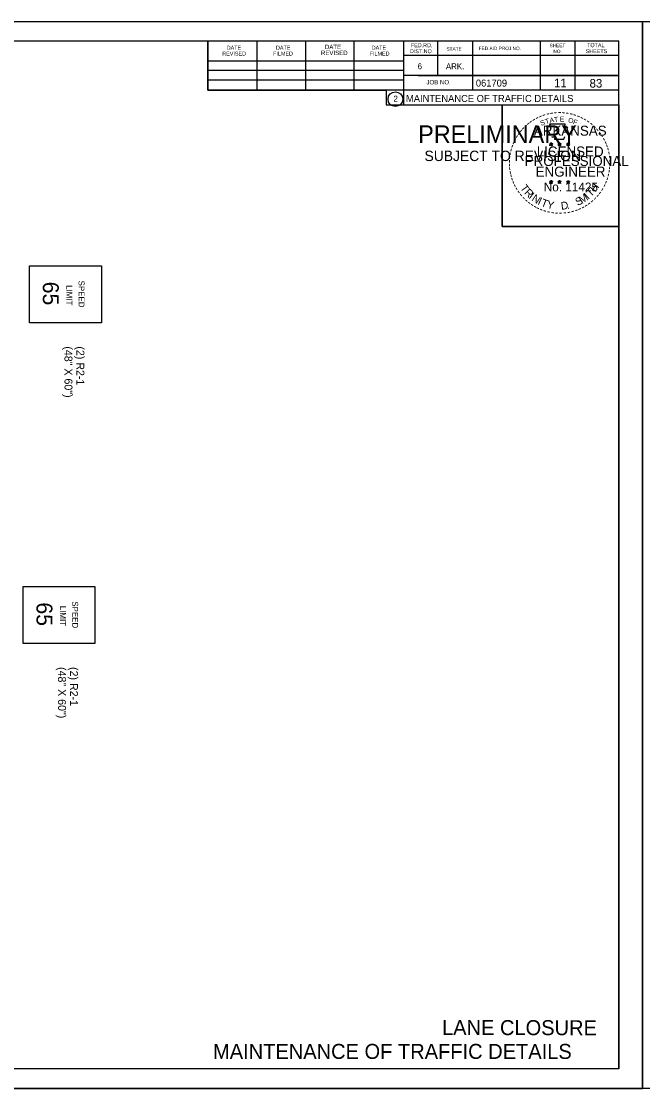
# Model space of a CAD drawing. Extents: x 1397271 to 1411271, y 376395 to 377888.
# Drawn here: x 1408068 to 1408938, y 376395 to 377888 of the extents above; entities that cross this region are included whole.
import ezdxf

# ---------------------------------------------------------------- set-up
doc = ezdxf.new("R2010")
doc.units = 0
for name, color, linetype in [('Default', 7, 'Continuous'), ('R_Border', 7, 'Continuous'), ('R_Border PE', 7, 'Continuous'), ('R_Border Prem', 7, 'Continuous'), ('R_Draft', 7, 'Continuous'), ('R_MOT', 7, 'Continuous'), ('R_No Plot', 7, 'Continuous')]:
    doc.layers.add(name, color=color, linetype=linetype)

msp = doc.modelspace()

# ---------------------------------------------------------------- linework, layer by layer
at = {"layer": 'R_Border'}
for p, q in [((1406691.4, 377860.7), (1408904.7, 377860.7)), ((1408328.9, 377791.6), (1408328.9, 377860.7)), ((1408397.9, 377791.6), (1408397.9, 377859.3)), ((1408466.2, 377791.6), (1408466.2, 377859.3)), ((1408534, 377791.6), (1408534, 377859.3)), ((1408603, 377860.7), (1408603, 377771.1)), ((1408650.9, 377860.7), (1408650.9, 377812.1)), ((1408699.5, 377860.7), (1408699.5, 377791.6)), ((1408794.5, 377860.7), (1408794.5, 377791.6)), ((1408843.1, 377860.7), (1408843.1, 377791.6)), ((1408904.7, 376422.5), (1408904.7, 377860.7)), ((1408328.9, 377832.6), (1408603, 377832.6)), ((1408904.7, 377840.1), (1408603, 377840.1)), ((1408904.7, 377840.3), (1408904.7, 377840.3)), ((1408328.9, 377819.6), (1408603, 377819.6)), ((1408328.9, 377791.6), (1408328.9, 377806)), ((1408328.9, 377806), (1408603, 377806)), ((1408904.7, 377812.1), (1408603, 377812.1)), ((1408623.7, 377812.1), (1408904.7, 377812.1)), ((1408904.7, 377791.6), (1408328.9, 377791.6)), ((1408603, 377771.1), (1408904.7, 377771.1)), ((1408904.7, 376422.5), (1406691.4, 376422.5))]:
    msp.add_line(p, q, dxfattribs=at)
msp.add_circle((1408591.7, 377779.1), 10.3, dxfattribs=at)
at = {"layer": 'R_Border PE'}
for p, q in [((1408807.3, 377716.8), (1408809.7, 377716.1)), ((1408807.3, 377716.8), (1408809.1, 377716.5)), ((1408807.3, 377716.8), (1408809, 377716)), ((1408808.2, 377714), (1408809.7, 377716.1)), ((1408808.2, 377714), (1408809.1, 377715.7)), ((1408808.2, 377714), (1408809.7, 377715.5)), ((1408809.7, 377718.6), (1408809.5, 377716.9)), ((1408809.7, 377716.1), (1408809.7, 377718.6)), ((1408809.7, 377718.6), (1408810.1, 377716.9)), ((1408812.2, 377716.8), (1408809.7, 377716.1)), ((1408811.2, 377714), (1408809.7, 377716.1)), ((1408811.2, 377714), (1408809.7, 377715.5)), ((1408812.2, 377716.8), (1408810.2, 377716.5)), ((1408811.2, 377714), (1408810.3, 377716)), ((1408812.2, 377716.8), (1408810.7, 377716.1)), ((1408819, 377716.8), (1408821.4, 377716.1)), ((1408819, 377716.8), (1408820.8, 377716.5)), ((1408819, 377716.8), (1408820.7, 377716)), ((1408819.9, 377714), (1408821.4, 377716.1)), ((1408819.9, 377714), (1408820.8, 377715.7)), ((1408819.9, 377714), (1408821.4, 377715.5)), ((1408821.4, 377718.6), (1408821.1, 377716.9)), ((1408821.4, 377716.1), (1408821.4, 377718.6)), ((1408821.4, 377718.6), (1408821.8, 377716.9)), ((1408823.9, 377716.8), (1408821.4, 377716.1)), ((1408822.9, 377714), (1408821.4, 377716.1)), ((1408822.9, 377714), (1408821.4, 377715.5)), ((1408823.9, 377716.8), (1408821.9, 377716.5)), ((1408822.9, 377714), (1408822, 377716)), ((1408823.9, 377716.8), (1408822.4, 377716.1)), ((1408831.3, 377716.8), (1408833.8, 377716)), ((1408831.3, 377716.8), (1408833.1, 377716.4)), ((1408831.3, 377716.8), (1408833, 377715.9)), ((1408832.3, 377713.9), (1408833.8, 377716)), ((1408832.3, 377713.9), (1408833.2, 377715.6)), ((1408832.3, 377713.9), (1408833.8, 377715.4)), ((1408833.8, 377718.5), (1408833.5, 377716.8)), ((1408833.8, 377716), (1408833.8, 377718.5)), ((1408833.8, 377718.5), (1408834.1, 377716.8)), ((1408836.2, 377716.8), (1408833.8, 377716)), ((1408835.3, 377713.9), (1408833.8, 377716)), ((1408835.3, 377713.9), (1408833.8, 377715.4)), ((1408836.2, 377716.8), (1408834.2, 377716.4)), ((1408835.3, 377713.9), (1408834.3, 377715.9)), ((1408836.2, 377716.8), (1408834.8, 377716)), ((1408807.3, 377663.8), (1408809.7, 377663.1)), ((1408807.3, 377663.8), (1408809, 377663.5)), ((1408807.3, 377663.8), (1408808.9, 377663)), ((1408809.7, 377665.6), (1408809.4, 377663.8)), ((1408809.7, 377663.1), (1408809.7, 377665.6)), ((1408809.7, 377665.6), (1408810.1, 377663.9)), ((1408812.1, 377663.8), (1408809.7, 377663.1)), ((1408812.1, 377663.8), (1408810.1, 377663.5)), ((1408812.1, 377663.8), (1408810.7, 377663.1)), ((1408819, 377663.8), (1408821.4, 377663.1)), ((1408819, 377663.8), (1408820.7, 377663.5)), ((1408819, 377663.8), (1408820.6, 377663)), ((1408821.4, 377665.6), (1408821.1, 377663.8)), ((1408821.4, 377663.1), (1408821.4, 377665.6)), ((1408821.4, 377665.6), (1408821.7, 377663.9)), ((1408823.8, 377663.8), (1408821.4, 377663.1)), ((1408823.8, 377663.8), (1408821.8, 377663.5)), ((1408823.8, 377663.8), (1408822.4, 377663.1)), ((1408831.3, 377663.8), (1408833.8, 377663)), ((1408831.3, 377663.8), (1408833.1, 377663.4)), ((1408831.3, 377663.8), (1408833, 377662.9)), ((1408833.8, 377665.5), (1408833.5, 377663.8)), ((1408833.8, 377663), (1408833.8, 377665.5)), ((1408833.8, 377665.5), (1408834.1, 377663.8)), ((1408836.2, 377663.8), (1408833.8, 377663)), ((1408836.2, 377663.8), (1408834.2, 377663.4)), ((1408836.2, 377663.8), (1408834.8, 377663)), ((1408808.2, 377661), (1408809.7, 377663.1)), ((1408808.2, 377661), (1408809.1, 377662.7)), ((1408808.2, 377661), (1408809.7, 377662.5)), ((1408811.2, 377661), (1408809.7, 377663.1)), ((1408811.2, 377661), (1408809.7, 377662.5)), ((1408811.2, 377661), (1408810.2, 377663)), ((1408819.9, 377661), (1408821.4, 377663.1)), ((1408819.9, 377661), (1408820.8, 377662.7)), ((1408819.9, 377661), (1408821.4, 377662.5)), ((1408822.9, 377661), (1408821.4, 377663.1)), ((1408822.9, 377661), (1408821.4, 377662.5)), ((1408822.9, 377661), (1408821.9, 377663)), ((1408832.3, 377660.9), (1408833.8, 377663)), ((1408832.3, 377660.9), (1408833.1, 377662.6)), ((1408832.3, 377660.9), (1408833.8, 377662.4)), ((1408835.3, 377660.9), (1408833.8, 377663)), ((1408835.3, 377660.9), (1408833.8, 377662.4)), ((1408835.3, 377660.9), (1408834.3, 377662.9))]:
    msp.add_line(p, q, dxfattribs=at)
for points in [[(1408807.6, 377744), (1408809.5, 377738.2)], [(1408832.2, 377737.5), (1408833.2, 377739.5), (1408828.4, 377739.4), (1408829.4, 377744), (1408807.6, 377744)], [(1408811, 377727), (1408811, 377726.4), (1408815, 377726.3), (1408814.6, 377723), (1408827.7, 377723), (1408829.1, 377726.7)], [(1408809.7, 377718.6), (1408811.2, 377714), (1408807.3, 377716.8), (1408812.2, 377716.8), (1408808.2, 377714), (1408809.7, 377718.6)], [(1408821.4, 377718.6), (1408822.9, 377714), (1408819, 377716.8), (1408823.9, 377716.8), (1408819.9, 377714), (1408821.4, 377718.6)], [(1408833.8, 377718.5), (1408835.3, 377713.9), (1408831.3, 377716.8), (1408836.2, 377716.8), (1408832.3, 377713.9), (1408833.8, 377718.5)], [(1408809.7, 377665.6), (1408811.2, 377661), (1408807.3, 377663.8), (1408812.1, 377663.8), (1408808.2, 377661), (1408809.7, 377665.6)], [(1408821.4, 377665.6), (1408822.9, 377661), (1408819, 377663.8), (1408823.8, 377663.8), (1408819.9, 377661), (1408821.4, 377665.6)], [(1408833.8, 377665.5), (1408835.3, 377660.9), (1408831.3, 377663.8), (1408836.2, 377663.8), (1408832.3, 377660.9), (1408833.8, 377665.5)]]:
    msp.add_lwpolyline(points, dxfattribs=at)
for centre, radius in [((1408809.7, 377716.1), 1.21), ((1408809.7, 377716.1), 1.01), ((1408809.7, 377716.1), 0.81), ((1408809.7, 377716.1), 0.694), ((1408809.7, 377716.1), 0.523), ((1408809.7, 377716.1), 0.347), ((1408809.7, 377716.1), 0.208), ((1408821.4, 377716.1), 1.21), ((1408821.4, 377716.1), 1.01), ((1408821.4, 377716.1), 0.81), ((1408821.4, 377716.1), 0.694), ((1408821.4, 377716.1), 0.523), ((1408821.4, 377716.1), 0.347), ((1408821.4, 377716.1), 0.208), ((1408833.8, 377716), 1.21), ((1408833.8, 377716), 1.01), ((1408833.8, 377716), 0.81), ((1408833.8, 377716), 0.694), ((1408833.8, 377716), 0.523), ((1408833.8, 377716), 0.347), ((1408833.8, 377716), 0.208), ((1408809.7, 377663), 1.21), ((1408809.7, 377663), 1.01), ((1408809.7, 377663), 0.81), ((1408809.7, 377663), 0.694), ((1408821.4, 377663), 1.21), ((1408821.4, 377663), 1.01), ((1408821.4, 377663), 0.81), ((1408821.4, 377663), 0.694), ((1408833.8, 377663), 1.21), ((1408833.8, 377663), 1.01), ((1408833.8, 377663), 0.81), ((1408833.8, 377663), 0.694), ((1408809.7, 377663), 0.523), ((1408809.7, 377663), 0.347), ((1408809.7, 377663), 0.208), ((1408821.4, 377663), 0.523), ((1408821.4, 377663), 0.347), ((1408821.4, 377663), 0.208), ((1408833.8, 377663), 0.523), ((1408833.8, 377663), 0.347), ((1408833.8, 377663), 0.208)]:
    msp.add_circle(centre, radius, dxfattribs=at)
at = {"layer": 'R_MOT'}
for points in [[(1408179.9, 377466.3), (1408079.5, 377466.3), (1408079.5, 377545.9), (1408179.9, 377545.9)], [(1408170.9, 377017.6), (1408070.6, 377017.6), (1408070.6, 377097.2), (1408170.9, 377097.2)]]:
    msp.add_lwpolyline(points, close=True, dxfattribs=at)
at = {"layer": 'R_No Plot'}
for p, q in [((1406604.6, 377888), (1408938, 377888)), ((1408736.9, 377613.9), (1408736.9, 377613.9)), ((1406604.6, 376394.6), (1408938, 376394.6))]:
    msp.add_line(p, q, dxfattribs=at)
for points in [[(1406604.6, 377888), (1408938, 377888), (1408938, 376394.6), (1406604.6, 376394.6)], [(1408938, 377888), (1411271.4, 377888), (1411271.4, 376394.6), (1408938, 376394.6)], [(1408328.9, 377860.7), (1408328.9, 377791.6), (1408579, 377791.6), (1408579, 377771.1), (1408741.4, 377771.1), (1408741.4, 377600.8), (1408904.7, 377600.8), (1408904.7, 376422.5), (1406691.4, 376422.5), (1406691.4, 377860.7)], [(1408741.4, 377771.3), (1408904.7, 377771.3), (1408904.7, 377600.8), (1408741.4, 377600.8)]]:
    msp.add_lwpolyline(points, close=True, dxfattribs=at)

# ---------------------------------------------------------------- texts
at = {"layer": 'Default'}
msp.add_text('LANE CLOSURE', height=21, rotation=359.9326, dxfattribs=at).set_placement((1408657, 376469.6))
at = {"layer": 'R_Border'}
for s, height, p in [('REVISED', 5.47, (1408349.3, 377840.1)), ('DATE', 5.47, (1408355.5, 377848.4)), ('FILMED', 5.47, (1408420.5, 377840.1)), ('DATE', 5.47, (1408424.5, 377848.4)), ('REVISED', 6.15, (1408487.5, 377840.8)), ('DATE', 6.15, (1408493, 377849.1)), ('FILMED', 5.47, (1408555.8, 377840.1)), ('DATE', 5.47, (1408558.6, 377848.4)), ('DIST.NO.', 5.47, (1408612, 377843.5)), ('FED.RD.', 5.47, (1408613.4, 377851.8)), ('STATE', 4.79, (1408663.2, 377847)), ('FED.AID PROJ.NO.', 4.788, (1408708.4, 377847.7)), ('SHEET', 4.79, (1408807.6, 377851.8)), ('NO.', 4.79, (1408813, 377843.5)), ('SHEETS', 5.47, (1408858.2, 377843.5)), ('TOTAL', 5.47, (1408860.2, 377851.8)), ('6', 8.21, (1408622.9, 377821)), ('ARK.', 8.21, (1408662.5, 377821)), ('JOB NO.', 6.15, (1408635.2, 377799.8)), ('061709', 9.8, (1408704.4, 377796.7)), ('2', 8.21, (1408589, 377775.7)), ('MAINTENANCE OF TRAFFIC DETAILS', 9.8, (1408606.5, 377775.2)), ('MAINTENANCE OF TRAFFIC DETAILS', 21, (1408336.3, 376436.2))]:
    msp.add_text(s, height=height, rotation=360, dxfattribs=at).set_placement(p)
at = {"layer": 'R_Border PE'}
for s, height, rotation, p in [('-', 11.2, 28.7918, (1408790, 377747.8)), ('-', 11.2, 24.3072, (1408794.4, 377750)), ('-', 11.2, 19.1761, (1408798.8, 377751.9)), ('-', 11.2, 13.6301, (1408804.1, 377753.6)), ('A', 7, 11.2132, (1408808.3, 377745.8)), ('-', 11.2, 10.2193, (1408808.8, 377754.7)), ('T', 7, 6.0228, (1408814.2, 377747)), ('-', 11.2, 5.8968, (1408813.9, 377755.5)), ('-', 11.2, 0.1862, (1408819.3, 377756)), ('E', 7, 0.8323, (1408821.9, 377747.7)), ('-', 11.2, 357.743, (1408824.4, 377755.9)), ('-', 11.2, 352.1617, (1408829.6, 377755.5)), ('-', 11.2, 347.2049, (1408834.6, 377754.7)), ('-', 11.2, 342.3362, (1408839.1, 377753.6)), ('-', 11.2, 337.8551, (1408844.2, 377752)), ('-', 11.2, 334.1211, (1408848.6, 377750.1)), ('-', 11.2, 48.423, (1408772.2, 377733.5)), ('-', 11.2, 42.9622, (1408775.4, 377736.9)), ('-', 11.2, 38.9507, (1408778.4, 377739.8)), ('-', 11.2, 36.2317, (1408781.7, 377742.4)), ('-', 11.2, 34.0636, (1408785.8, 377745.2)), ('ARKANSAS', 14, 360, (1408785.6, 377728)), ('S', 7, 21.594, (1408796.1, 377741.7)), ('T', 7, 16.4036, (1408802.5, 377744.1)), ('O', 7, 350.4515, (1408833.2, 377746.3)), ('F', 7, 340.0707, (1408839.8, 377744.7)), ('-', 11.2, 329.6409, (1408852.7, 377748.2)), ('-', 11.2, 325.8627, (1408857.2, 377745.6)), ('-', 11.2, 320.5297, (1408861.5, 377742.7)), ('-', 11.2, 315.5786, (1408865.7, 377739.2)), ('-', 11.2, 62.8713, (1408762.1, 377718.1)), ('-', 11.2, 58.0706, (1408764.2, 377722.4)), ('-', 11.2, 54.2325, (1408766.5, 377726.1)), ('-', 11.2, 50.6142, (1408769.4, 377730.1)), ('-', 11.2, 309.8797, (1408869.6, 377735.4)), ('-', 11.2, 306.6522, (1408873.3, 377731.2)), ('-', 9.8, 303.6753, (1408876.7, 377727.2)), ('-', 11.2, 299.6684, (1408878.9, 377723)), ('-', 11.2, 75.461, (1408757.3, 377704.5)), ('-', 11.2, 72.3945, (1408758.7, 377709.5)), ('-', 11.2, 67.7743, (1408760.2, 377713.9)), ('LICENSED', 14, 360, (1408789.7, 377698.9)), ('DWB', 0.07, 360, (1408809.7, 377716)), ('DWB', 0.07, 360, (1408821.3, 377716)), ('DWB', 0.07, 360, (1408833.7, 377716)), ('-', 11.2, 294.6628, (1408881.2, 377718.7)), ('-', 11.2, 290.5728, (1408883, 377714.6)), ('-', 11.2, 285.1233, (1408884.7, 377710.6)), ('-', 11.2, 89.0622, (1408755.7, 377689.7)), ('-', 11.2, 85.1863, (1408755.9, 377694.6)), ('-', 11.2, 81.2013, (1408756.4, 377699.5)), ('PROFESSIONAL', 14, 360, (1408772.8, 377685.6)), ('-', 11.2, 280.5493, (1408886.1, 377705.4)), ('-', 11.2, 276.5962, (1408887.2, 377700)), ('-', 11.2, 274.3301, (1408887.6, 377694.9)), ('-', 11.2, 94.1959, (1408755.9, 377684.7)), ('-', 11.2, 98.9479, (1408756.4, 377680)), ('ENGINEER', 14, 360, (1408788.1, 377670.7)), ('-', 11.2, 260.9953, (1408887.2, 377681.3)), ('-', 11.2, 263.5172, (1408887.7, 377685.9)), ('-', 11.2, 269.9407, (1408887.8, 377690.5)), ('-', 11.2, 101.7149, (1408757.4, 377674.9)), ('-', 11.2, 105.4578, (1408758.5, 377670.7)), ('-', 11.2, 109.0874, (1408760, 377666.3)), ('-', 11.2, 114.0643, (1408761.8, 377662.1)), ('-', 11.2, 247.8887, (1408883.6, 377666.8)), ('-', 11.2, 252.8681, (1408885.2, 377671.5)), ('-', 11.2, 255.7626, (1408886.4, 377676.5)), ('-', 11.2, 115.7289, (1408763.9, 377657.8)), ('-', 11.2, 120.4471, (1408766.4, 377653.7)), ('-', 11.2, 125.8934, (1408769.3, 377649.7)), ('T', 10.8, 306.0406, (1408766, 377654.9)), ('R', 10.8, 314.005, (1408771.4, 377647.6)), ('I', 10.8, 321.9694, (1408777.7, 377641.1)), ('No. 11425', 12.3, 360, (1408799.5, 377650.1)), ('DWB', 0.07, 360, (1408809.6, 377663)), ('DWB', 0.07, 360, (1408821.3, 377663)), ('DWB', 0.07, 360, (1408833.7, 377662.9)), ('T', 10.8, 46.6444, (1408865.6, 377641.6)), ('H', 10.8, 54.6088, (1408871.9, 377648.2)), ('-', 11.2, 233.8452, (1408876.2, 377652.5)), ('-', 11.2, 239.0712, (1408879, 377657.1)), ('-', 11.2, 244.6197, (1408881.8, 377662.4)), ('-', 11.2, 130.7181, (1408772.5, 377645.9)), ('-', 11.2, 134.2238, (1408776.1, 377642.1)), ('-', 11.2, 138.9338, (1408779.8, 377638.8)), ('-', 11.2, 144.6463, (1408783.7, 377636)), ('N', 10.8, 326.5002, (1408781.6, 377637.8)), ('I', 10.8, 335.3603, (1408790.1, 377632.3)), ('T', 10.8, 339.8912, (1408794.7, 377630)), ('Y', 10.8, 347.8556, (1408803.2, 377626.8)), ('D', 10.8, 6.3969, (1408824.1, 377624.3)), ('S', 10.8, 26.9312, (1408846.9, 377629.5)), ('M', 10.8, 32.6563, (1408852.7, 377632.3)), ('I', 10.8, 42.1136, (1408861.7, 377638.2)), ('-', 11.2, 215.7363, (1408862.3, 377637.8)), ('-', 11.2, 221.0851, (1408866.2, 377641.1)), ('-', 11.2, 225.7653, (1408869.8, 377644.6)), ('-', 11.2, 231.2538, (1408873.2, 377648.6)), ('-', 11.2, 148.0898, (1408787.6, 377633.4)), ('-', 11.2, 151.5704, (1408791.7, 377631.1)), ('-', 11.2, 154.6002, (1408795.3, 377629.4)), ('-', 11.2, 158.5612, (1408799.7, 377627.6)), ('-', 11.2, 162.7983, (1408804.5, 377626.1)), ('-', 11.2, 167.5555, (1408809.5, 377625)), ('-', 11.2, 173.1155, (1408814.9, 377624.2)), ('-', 11.2, 176.5183, (1408820.1, 377623.8)), ('-', 11.2, 181.5918, (1408825.3, 377623.9)), ('-', 11.2, 185.8167, (1408831, 377624.5)), ('-', 11.2, 191.2858, (1408836.2, 377625.4)), ('.', 10.8, 13.7642, (1408832.5, 377625.2)), ('-', 11.2, 195.4743, (1408841.3, 377626.8)), ('-', 11.2, 200.7184, (1408846, 377628.5)), ('-', 11.2, 204.2516, (1408850.3, 377630.4)), ('-', 11.2, 207.3568, (1408854.7, 377632.6)), ('-', 11.2, 212.2491, (1408858.6, 377635.1))]:
    msp.add_text(s, height=height, rotation=rotation, dxfattribs=at).set_placement(p)
at = {"layer": 'R_Border Prem'}
for s, height, p in [('PRELIMINARY', 24.5, (1408623.6, 377717.9)), ('DWB', 0.07, (1408625.1, 377730.9)), ('SUBJECT TO REVISION', 14.526, (1408632.5, 377692.5))]:
    msp.add_text(s, height=height, rotation=360, dxfattribs=at).set_placement(p)
at = {"layer": 'R_Draft'}
for s, p in [('11', (1408813.8, 377795.7)), ('83', (1408863.6, 377795.3))]:
    msp.add_text(s, height=12, rotation=360, dxfattribs=at).set_placement(p)
at = {"layer": 'R_MOT'}
for s, height, p in [('65', 22.23, (1408098, 377523.7)), ('LIMIT', 8.3, (1408130.9, 377518.9)), ('SPEED', 8.3, (1408148, 377525.2)), ('(48" X 60")', 11.115, (1408128.3, 377433.2)), ('(2) R2-1', 11.12, (1408145, 377433.2)), ('65', 22.23, (1408089.1, 377075)), ('LIMIT', 8.3, (1408122, 377070.2)), ('SPEED', 8.3, (1408139.1, 377076.5)), ('(48" X 60")', 11.115, (1408119.3, 376984.5)), ('(2) R2-1', 11.12, (1408136, 376984.5))]:
    msp.add_text(s, height=height, rotation=270, dxfattribs=at).set_placement(p)

doc.saveas('drawing.dxf')
